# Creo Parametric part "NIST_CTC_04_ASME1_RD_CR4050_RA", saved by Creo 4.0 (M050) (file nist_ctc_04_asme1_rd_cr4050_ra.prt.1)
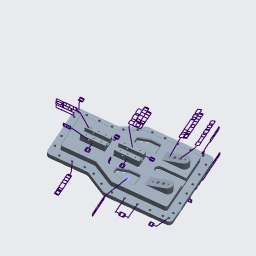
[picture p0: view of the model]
Units: millimeter Kilogram Sec (mmKs); MM, KILOGRAM, SECS

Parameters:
  PART_NUMBER = "NIST PMI CTC 04 ASME1"
  REVISION = "D"
  DESCRIPTION = "NIST PMI test model downloaded from http://go.usa.gov/mGVm"
  METRIC = "YES"
  SCREW_SIZE = "M12x1.75"

Other parameters: PITCH, DRILL_POINT_ANGLE, DRILL_DEPTH, DRILL_DIAMETER, THREAD_DIAMETER, THREADS_PER_INCH, THREAD_DEPTH, THREAD_LENGTH

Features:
  1. datum plane "RIGHT"
  2. datum plane "TOP"
  3. datum plane "FRONT"
  4. coordinate system
  5. curve
  6. protrusion
  7. curve
  8. pattern
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
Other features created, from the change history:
  feature "Designate Area 1"

Other named items: PROFILE-REGION, CS0, CS1, CS2, CS3, CS4, CS5, DATUM_TAG_A, DATUM_TAG_B, AD1055, AD1059, AD1062, AD1067, AD1068, AD1070, AD1072, AD1074, GP8, DRF1, DATUM_TAG_C, DATUM_TAG_D, DATUM_TAG_E, DATUM_TAG_F, DATUM_TAG_G, DATUM_TAG_H, AD1075, GP9, DRF2, DRF3, GP10, GP11, AD1076, GP12, DRF4, DRF5, MBD_0, ANNOT_LAYER_STATE0018

Notes:  j|n 0.35 | A | B | C

Family table entries: GENERIC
